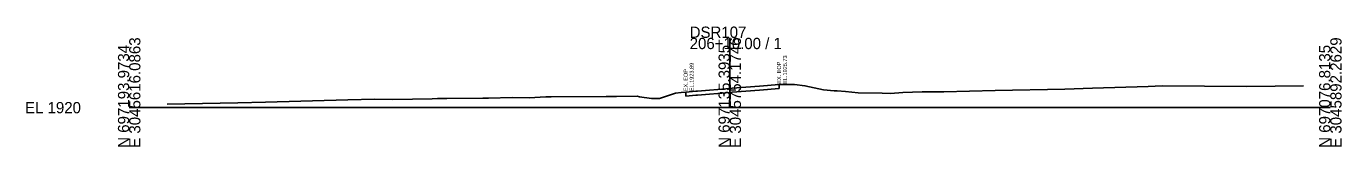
# Model space of a CAD drawing. Extents: x -26 to 19003, y -31 to 24541.
# Drawn here: x 1974.3 to 2302.8, y 8490.3 to 8520.2 of the extents above; entities that cross this region are included whole.
import ezdxf

# ---------------------------------------------------------------- set-up
doc = ezdxf.new("R2010")
doc.units = 0
for name, color, linetype in [('DESIGN - SHEET - Light Grid', 7, 'Continuous'), ('SURVEY - GROUND - Existing Pavement Layer', 7, 'Continuous'), ('SURVEY - GROUND - Existing Pavement Text', 7, 'Continuous'), ('SURVEY - GROUND - Top of Ground', 7, 'Continuous')]:
    doc.layers.add(name, color=color, linetype=linetype)

msp = doc.modelspace()

# ---------------------------------------------------------------- linework, layer by layer
at = {"layer": 'DESIGN - SHEET - Light Grid'}
for p, q in [((2150, 8500), (2150, 8517.37)), ((2000, 8500), (2150, 8500)), ((2150, 8500), (2300, 8500))]:
    msp.add_line(p, q, dxfattribs=at)
at = {"layer": 'SURVEY - GROUND - Existing Pavement Layer'}
for p, q in [((2162.31, 8505.73), (2162.31, 8504.73)), ((2138.99, 8502.89), (2138.99, 8503.89)), ((2138.99, 8502.89), (2141.5, 8503.08)), ((2141.5, 8503.08), (2141.96, 8503.11)), ((2141.96, 8503.11), (2150, 8503.77)), ((2150, 8503.77), (2150.57, 8503.82)), ((2150.57, 8503.82), (2157.39, 8504.35)), ((2157.39, 8504.35), (2162.31, 8504.73))]:
    msp.add_line(p, q, dxfattribs=at)
at = {"layer": 'SURVEY - GROUND - Top of Ground'}
msp.add_lwpolyline([(2009.47, 8500.84), (2027.12, 8501.21), (2034.07, 8501.38), (2054.62, 8501.91), (2061.38, 8502.08), (2065.89, 8502.05), (2075.71, 8502.17), (2076.98, 8502.24), (2079.37, 8502.3), (2088.34, 8502.38), (2089.76, 8502.37), (2095.62, 8502.49), (2099.93, 8502.42), (2104.06, 8502.68), (2105.36, 8502.69), (2119.14, 8502.78), (2121.68, 8502.79), (2126.91, 8502.83), (2127.43, 8502.72), (2130.43, 8502.25), (2131.69, 8502.26), (2132.46, 8502.27), (2134.98, 8503.08), (2136.45, 8503.6), (2137.85, 8503.75), (2138.99, 8503.89), (2141.5, 8504.08), (2141.96, 8504.11), (2150, 8504.77), (2150.57, 8504.82), (2157.39, 8505.35), (2162.31, 8505.73), (2163.02, 8505.76), (2163.5, 8505.79), (2165.16, 8505.78), (2166.16, 8505.76), (2168.76, 8505.44), (2173.44, 8504.43), (2176.06, 8504.19), (2176.8, 8504.16), (2178.87, 8503.98), (2182.07, 8503.67), (2188.07, 8503.59), (2190.15, 8503.51), (2193.21, 8503.74), (2198.05, 8503.95), (2203.47, 8503.9), (2216.26, 8504.28), (2233.65, 8504.62), (2240.64, 8504.87), (2254.53, 8505.25), (2257.96, 8505.44), (2279.15, 8505.28), (2293.34, 8505.42)], dxfattribs=at)

# ---------------------------------------------------------------- texts
at = {"layer": 'DESIGN - SHEET - Light Grid'}
for s, p in [('DSR107', (2140, 8517.37)), ('206+10.00 / 1', (2140, 8514.57)), ('EL 1920', (1974, 8498.6))]:
    msp.add_text(s, height=2.8, dxfattribs=at).set_placement(p)
for s, p in [('E 3045616.0863', (2002.8, 8490)), ('E 3045754.1746', (2152.8, 8490)), ('E 3045892.2629', (2302.8, 8490)), ('N 697193.9734', (2000, 8490)), ('N 697135.3935', (2150, 8490)), ('N 697076.8135', (2300, 8490))]:
    msp.add_text(s, height=2.8, rotation=90, dxfattribs=at).set_placement(p)
at = {"layer": 'SURVEY - GROUND - Existing Pavement Text'}
for s, p in [('EL.1925.73', (2164.31, 8505.93)), ('EX. EOP', (2139.49, 8504.09)), ('EL.1923.89', (2141, 8504.09)), ('EX. EOP', (2162.81, 8505.93))]:
    msp.add_text(s, height=1, rotation=90, dxfattribs=at).set_placement(p)

doc.saveas('drawing.dxf')
